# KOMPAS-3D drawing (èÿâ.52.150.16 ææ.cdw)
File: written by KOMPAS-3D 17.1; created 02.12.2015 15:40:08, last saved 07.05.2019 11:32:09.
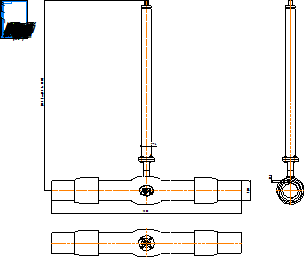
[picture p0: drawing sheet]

Sheet 1: A4, portrait

Title block, sheet 1: name: КШГ.52.150.16 СС; material: Внимание! Данный продукт является объектом авторского права ООО «Торговый Дом АДЛ». / Запрещается изменение, копирование, распространение / (в том числе путем копирования на другие сайты и ресурсы в Интернете) / или любое иное использование информации и объектов без предварительного / согласия правообладателя (ООО «Торговый Дом АДЛ»).; sheets: 1; organisation: ООО "Торговый дом АДЛ"; sheet format: A4; stored path: C:\Users\kka\KOMPAS_Work\Модели кранов для исследований\DN50\С удлинением\КШГ.32.050.40 СС ГЧ _ Шаровой кран БИВАЛ Ду50 Ру4 МПа редуцированный под приварку, с удлинением штока H=1100.cdw; drawn by: Климкович К.А.; drawn by, date: 07.12.16

Views: Вид 1, Проекционный вид 2
Referenced files in C:\Users\kka\KOMPAS_Work\Модели кранов для исследований\DN80\С удлинением\: КШТ.22.080.25 СС.a3d
Referenced files in C:\Users\kka\KOMPAS_Work\Модели кранов для исследований\DN150\С удлинением\: КШТ.22.150.25 СС.a3d, КШГ.35.125.25 СС Lстр600.a3d, КШГ.35.125.25 СС Lстр600.a3d!Деталь (локальная).m3d
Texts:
  Klimkovich
  ADL
  (от 480 до 5000)
Dimensions and other numbers on the sheet: 76; 160; 1500; 17,9; 1:1; 1; 07.12.16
